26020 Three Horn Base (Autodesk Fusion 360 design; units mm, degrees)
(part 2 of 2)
sketch "Branding Profile 1" plane through (0, -3.9688, 0) normal (0, -1, 0) x axis (1, 0, 0)
  line L1 (-31.5508, 186.9488) -> (-36.5959, 184.036)
  line L2 (-12.7, 222.2105) -> (-12.7, 219.5994)
  line L3 (-155.7294, 176.3331) -> (-12.7, 222.2105)
  line L4 (-155.575, 165.6244) -> (-155.575, 174.625)
  line L5 (-56.8347, 186.3809) -> (-136.4794, 160.8345)
  line L6 (-56.8347, 186.3809) -> (-56.3499, 184.8693)
  line L7 (-136.4794, 160.8345) -> (-56.8347, 186.3809)
  line L8 (-135.9945, 159.3229) -> (-136.4794, 160.8345)
  line L9 (-56.3499, 184.8693) -> (-135.9945, 159.3229)
  curve K1 (-40.4845, 180.5516) -> (-40.1097, 176.7109)
  line L10 (-56.8347, 186.3809) -> (-56.3499, 184.8693)
  line L11 (-39.7709, 172.7761) -> (-39.77, 172.7761)
  curve K2 (-40.1097, 176.7109) -> (-39.77, 172.7761)
  curve K3 (-140.7089, 150.0191) -> (-141.9327, 154.2492)
  line L12 (-139.7584, 150.4844) -> (-140.7089, 150.0191)
  line L13 (-135.9945, 159.3229) -> (-136.4794, 160.8345)
  line L14 (-12.7, 222.2105) -> (-13.6697, 225.2338)
  line L15 (-156.6991, 179.3564) -> (-13.6697, 225.2338)
  line L16 (-156.6991, 179.3564) -> (-155.7294, 176.3331)
  line L17 (-12.7, 222.2105) -> (-155.7294, 176.3331)
  line L18 (136.4794, 160.8345) -> (56.8347, 186.3809)
  line L19 (155.575, 174.625) -> (155.575, 165.6244)
  line L20 (12.7, 222.2105) -> (155.7294, 176.3331)
  line L21 (12.7, 219.5994) -> (12.7, 222.2105)
  line L22 (36.5959, 184.036) -> (31.5508, 186.9488)
  curve K4 (40.4845, 180.5516) -> (40.1097, 176.7109)
  curve K5 (40.1097, 176.7109) -> (39.77, 172.7761)
  line L23 (39.7709, 172.7761) -> (39.77, 172.7761)
  line L24 (56.8347, 186.3809) -> (56.3499, 184.8693)
  line L25 (56.8347, 186.3809) -> (56.3499, 184.8693)
  line L26 (135.9945, 159.3229) -> (56.3499, 184.8693)
  line L27 (135.9945, 159.3229) -> (136.4794, 160.8345)
  line L28 (56.8347, 186.3809) -> (136.4794, 160.8345)
  line L29 (12.7, 222.2105) -> (13.6697, 225.2338)
  line L30 (155.7294, 176.3331) -> (12.7, 222.2105)
  line L31 (156.6991, 179.3564) -> (155.7294, 176.3331)
  line L32 (13.6697, 225.2338) -> (156.6991, 179.3564)
  curve K6 (140.7089, 150.0191) -> (141.9327, 154.2492)
  line L33 (135.9945, 159.3229) -> (136.4794, 160.8345)
  line L34 (139.7584, 150.4844) -> (140.7089, 150.0191)
  line L35 (155.575, 166.3797) -> (26.6705, 207.7264)
  line L36 (152.4473, 164.0486) -> (28.8842, 203.682)
  line L37 (54.1881, 192.6481) -> (54.5517, 193.7819)
  line L38 (89.7232, 181.2501) -> (54.1881, 192.6481)
  line L39 (90.0869, 182.3838) -> (89.7232, 181.2501)
  line L40 (54.5517, 193.7819) -> (90.0869, 182.3838)
  line L41 (56.0063, 198.3168) -> (54.5517, 193.7819)
  line L42 (91.5415, 186.9187) -> (90.0869, 182.3838)
  line L43 (0, 0) -> (0, 190.5)
  line L44 (-155.575, 166.3797) -> (-26.6705, 207.7264)
  line L45 (-152.4473, 164.0486) -> (-28.8842, 203.682)
  line L46 (-77.4266, 178.1088) -> (-84.2147, 199.2718)
  line L47 (-96.9368, 188.7387) -> (-96.6586, 188.1926)
  line L48 (-96.5087, 190.4673) -> (-99.5707, 189.4851)
  line L49 (-98.0524, 187.6309) -> (-98.1815, 188.0333)
  line L50 (-98.1815, 188.0333) -> (-98.2508, 188.2492)
  line L51 (-86.6058, 181.1557) -> (-90.1291, 180.4947)
  line L52 (-103.3725, 187.5824) -> (-101.9285, 187.6866)
  line L53 (-107.3077, 171.8767) -> (-112.6516, 188.5369)
  line L54 (-82.1059, 190.2631) -> (-81.3786, 187.9956)
  line L55 (-89.3894, 182.2487) -> (-86.9965, 182.6976)
  line L56 (-103.5297, 173.7717) -> (-105.8079, 171.5106)
  line L57 (-83.5117, 181.3674) -> (-84.351, 181.3852)
  line L58 (-97.996, 178.515) -> (-97.8569, 178.0814)
  line L59 (-102.0903, 183.4417) -> (-102.4361, 183.3308)
  line L60 (-87.2075, 194.612) -> (-83.1254, 181.8854)
  line L61 (-81.1219, 188.4947) -> (-80.5926, 188.6645)
  line L62 (-82.1059, 190.2631) -> (-83.84, 195.6696)
  line L63 (-96.9704, 182.637) -> (-97.3337, 182.5205)
  line L64 (-92.3853, 180.179) -> (-93.576, 183.8912)
  line L65 (-97.5904, 182.0213) -> (-96.569, 178.8371)
  line L66 (-95.8113, 180.3226) -> (-96.4713, 182.3803)
  line L67 (-96.0699, 178.5804) -> (-92.642, 179.6799)
  line L68 (-94.2583, 180.8208) -> (-94.9263, 182.9036)
  line L69 (-94.52, 180.3118) -> (-95.3023, 180.0609)
  line L70 (-93.2211, 191.7577) -> (-93.9769, 191.5153)
  line L71 (-97.989, 188.7582) -> (-97.421, 188.9404)
  line L72 (-99.114, 186.4379) -> (-99.8914, 188.8615)
  line L73 (-95.496, 188.6717) -> (-95.9857, 190.1983)
  line L74 (-105.4225, 174.2801) -> (-104.5257, 175.1702)
  line L75 (-100.2676, 177.79) -> (-98.7685, 178.7857)
  line L76 (-101.2759, 182.5708) -> (-101.4496, 183.1122)
  line L77 (-102.2104, 175.7615) -> (-106.2084, 188.2258)
  line L78 (-102.1328, 189.1978) -> (-105.727, 188.9383)
  line L79 (-111.2105, 188.9864) -> (-111.9726, 189.2226)
  line L80 (-103.4599, 174.9101) -> (-103.3418, 174.5419)
  line L81 (-103.0768, 183.6603) -> (-102.2807, 181.1784)
  line L82 (-106.3418, 174.5044) -> (-110.883, 188.6622)
  line L83 (-101.429, 188.426) -> (-101.5503, 188.8042)
  line L84 (-101.3112, 178.1557) -> (-102.2807, 181.1784)
  line L85 (-98.0769, 177.4536) -> (-101.1723, 175.3977)
  line L86 (-101.9512, 181.8191) -> (-101.6054, 181.93)
  line L87 (-103.0768, 183.6603) -> (-104.025, 186.6165)
  line L88 (-76.5065, 181.703) -> (-76.7732, 182.5347)
  line L89 (-89.8405, 182.5175) -> (-92.722, 191.501)
  line L90 (-80.3359, 189.1636) -> (-80.5783, 189.9194)
  line L91 (-88.4954, 194.306) -> (-87.8231, 194.8087)
  line L92 (-81.8448, 198.0238) -> (-82.108, 198.8442)
  line L93 (-80.6622, 181.6375) -> (-76.9319, 181.1878)
  line L94 (-91.0313, 181.0324) -> (-94.2336, 191.0162)
  line L95 (-83.7208, 196.0918) -> (-81.964, 197.6016)
  line L96 (-81.323, 182.1832) -> (-85.7039, 195.8413)
  line L97 (-81.0775, 190.1761) -> (-81.6067, 190.0064)
  line L98 (-95.5178, 183.7123) -> (-98.8586, 186.0887)
  line L99 (-94.1674, 184.6999) -> (-97.797, 187.2817)
  line L100 (-79.8972, 183.3773) -> (-81.3786, 187.9956)
  line L101 (-82.7445, 199.024) -> (-85.4654, 196.6857)
  line L102 (-84.7205, 181.6608) -> (-88.6357, 193.8669)
  line L103 (-86.5454, 182.4287) -> (-86.3011, 181.667)
  line L104 (-77.1036, 182.8075) -> (-79.5668, 183.1045)
  arc A1 centre (-30.2459, 173.0375) radius 12.7 clockwise from (-40.4845, 180.5516) to (-36.5959, 184.036)
  arc A2 centre (0, 190.5) radius 31.75 clockwise from (-31.5508, 186.9488) to (-12.7, 219.5994)
  arc A3 centre (-165.1, 174.625) radius 9.525 clockwise from (-155.7294, 176.3331) to (-155.575, 174.625)
  arc A4 centre (-168.275, 136.525) radius 31.75 clockwise from (-155.575, 165.6244) to (-141.9327, 154.2492)
  arc A5 centre (-134.0551, 153.2763) radius 7.9375 clockwise from (-141.9327, 154.2492) to (-136.4794, 160.8345)
  arc A6 centre (-52.4709, 172.7761) radius 14.2875 clockwise from (-56.8347, 186.3809) to (-40.4845, 180.5516)
  arc A7 centre (-52.4709, 172.7761) radius 14.2875 clockwise from (-56.8347, 186.3809) to (-40.4845, 180.5516)
  arc A8 centre (-52.4709, 172.7761) radius 12.7 clockwise from (-56.3499, 184.8693) to (-39.7709, 172.7761)
  arc A9 centre (-134.0551, 153.2763) radius 6.35 clockwise from (-139.7584, 150.4844) to (-135.9945, 159.3229)
  arc A10 centre (-134.0551, 153.2763) radius 7.9375 clockwise from (-141.9327, 154.2492) to (-136.4794, 160.8345)
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  point P79 (155.575, 166.3797)
  point P86 (56.0063, 198.3168)
  point P87 (91.5415, 186.9187)
  point P56 (0, 190.5)
  point P88 (0, 190.5)
  point P1 (0, 0)
  point P89 (0, 0)
  point P78 (26.6705, 207.7264)
  point P90 (-26.6705, 207.7264)
  point P91 (-155.575, 166.3797)
  point P80 (28.8842, 203.682)
  point P92 (-28.8842, 203.682)
  point P81 (152.4473, 164.0486)
  point P93 (-152.4473, 164.0486)
  point P94 (-84.2147, 199.2718)
  point P95 (-77.4266, 178.1088)
  point P124 (-106.3418, 174.5044)
  point P138 (-106.3418, 174.5044)
  point P220 (-89.8405, 182.5175)
  point P223 (-89.8405, 182.5175)
  point P239 (-80.4571, 189.5415)
  point P198 (-81.323, 182.1832)
  point P240 (-81.323, 182.1832)
  point P82 (54.5517, 193.7819)
  point P83 (54.1881, 192.6481)
  parallel L32 L35
  coincident L19 P79
  parallel L35 L36
  perpendicular L37 L38
  perpendicular L38 L39
  perpendicular L37 L40
  parallel L36 L40
  coincident L35 P86
  perpendicular L35 L41
  coincident L35 P87
  perpendicular L35 L42
  coincident P56 P88
  coincident P1 P89
  symmetric P78 L43 P90
  symmetric P79 L43 P91
  symmetric P80 L43 P92
  symmetric P81 L43 P93
  midpoint L3 P94
  coincident L9 P95
  perpendicular L9 L46
  parallel L56 L74
  coincident P124 P138
  parallel L52 L78
  parallel L75 L85
  parallel L49 L50
  parallel L98 L99
  parallel L51 L55
  coincident P220 P223
  parallel L95 L101
  midpoint P239 L90
  parallel L93 L104
  coincident P198 P240
  dimension "d207" distance L26 L35 = 12.7 (= "( 1 / 2 ) * 1 in")
  dimension "d208" distance L35 L36 = 3.175 (= "( 1 / 8 ) * 1 in")
  dimension "d210" distance P82 P83 = 1.1906 (= "( 3 / 64 ) * 1 in")
  dimension "d211" distance L36 L40 = 1.5875 (= "( 1 / 16 ) * 1 in")
  dimension "d277" angle L53 L79 = 55
  dimension "d278" distance L53 L82 = 1.7223
  dimension "d279" angle L53 L56 = 63
  dimension "d280" distance L77 L87 = 1.5875 (= "( 1 / 16 ) * 1 in")
  dimension "d281" radius = 0.5095
  dimension "d282" radius = 0.5095 (= "d281")
  dimension "d283" radius = 0.5095 (= "d281")
  dimension "d284" radius = 0.5095 (= "d281")
  dimension "d285" distance L59 L86 = 1.5875 (= "( 1 / 16 ) * 1 in")
  dimension "d287" radius = 0.4159
  dimension "d288" angle L47 L73 = 9.219
  dimension "d289" radius = 0.6307
  dimension "d290" radius = 0.4047
  dimension "d291" radius = 0.4047 (= "d290")
  dimension "d292" radius = 0.6854
  dimension "d293" radius = 0.6854 (= "d292")
  dimension "d294" distance L98 L99 = 1.5875 (= "( 1 / 16 ) * 1 in")
  dimension "d295" distance L64 L68 = 1.5875 (= "( 1 / 16 ) * 1 in")
  dimension "d296" radius = 1.5875 (= "( 1 / 16 ) * 1 in")
  dimension "d297" radius = 1.5875 (= "d296")
  dimension "d298" radius = 0.3969 (= "( 1 / 64 ) * 1 in")
  dimension "d299" radius = 0.3969 (= "( 1 / 64 ) * 1 in")
  dimension "d300" radius = 0.3969 (= "( 1 / 64 ) * 1 in")
  dimension "d301" radius = 0.3969 (= "d300")
  dimension "d302" radius = 0.4047 (= "d290")
  dimension "d303" radius = 0.4047 (= "d302")
  dimension "d304" distance L65 L66 = 1.1753 (= "d305")
  dimension "d305" distance L48 L71 = 1.1753
  dimension "d306" distance L67 L69 = 1.1753 (= "d305")
  dimension "d307" radius = 0.3969 (= "( 1 / 64 ) * 1 in")
  dimension "d308" radius = 0.3969 (= "d307")
  dimension "d309" distance L89 L94 = 1.5875 (= "( 1 / 16 ) * 1 in")
  dimension "d310" radius = 0.7937 (= "( 1 / 32 ) * 1 in")
  dimension "d311" radius = 0.3969 (= "( 1 / 64 ) * 1 in")
  dimension "d312" radius = 0.3969 (= "( 1 / 64 ) * 1 in")
  dimension "d313" distance L51 L55 = 1.5875 (= "( 1 / 16 ) * 1 in")
  dimension "d314" radius = 0.3969 (= "( 1 / 64 ) * 1 in")
  dimension "d317" radius = 0.3969 (= "( 1 / 64 ) * 1 in")
  dimension "d318" angle L57 L102 = 109
  dimension "d319" radius = 0.3969 (= "( 1 / 64 ) * 1 in")
  dimension "d320" distance L60 L102 = 1.5875 (= "( 1 / 16 ) * 1 in")
  dimension "d321" radius = 0.3969 (= "( 1 / 64 ) * 1 in")
  dimension "d322" radius = 0.3969 (= "( 1 / 64 ) * 1 in")
  dimension "d323" angle L91 L102 = 109
  dimension "d324" radius = 0.7937 (= "( 1 / 32 ) * 1 in")
  dimension "d326" radius = 0.3969 (= "( 1 / 64 ) * 1 in")
  dimension "d327" radius = 0.3969 (= "( 1 / 64 ) * 1 in")
  dimension "d328" distance L95 L101 = 1.5875 (= "( 1 / 16 ) * 1 in")
  dimension "d329" distance L62 L96 = 1.7223 (= "d278")
  dimension "d330" radius = 0.3969 (= "( 1 / 64 ) * 1 in")
  dimension "d331" radius = 0.3969 (= "d330")
  dimension "d332" distance L62 L90 = 1.3496
  dimension "d333" radius = 0.3969 (= "d330")
  dimension "d334" distance L61 L97 = 1.5875 (= "( 1 / 16 ) * 1 in")
  dimension "d335" radius = 0.3969 (= "d330")
  dimension "d336" radius = 0.3969 (= "( 1 / 64 ) * 1 in")
  dimension "d337" radius = 0.3969 (= "d336")
  dimension "d338" radius = 0.3969 (= "d337")
  dimension "d339" angle L88 L104 = 114.659
  dimension "d340" radius = 0.3969 (= "( 1 / 64 ) * 1 in")
  dimension "d342" distance L93 L104 = 1.5875 (= "( 1 / 16 ) * 1 in")
  dimension "d209" Text1-Height = 11.1125 (= "( 7 / 16 ) * 1 in")
extrude "Extrude17" add sketch "Branding Profile 1" along normal blind 0.3969 (= "( 1 / 64 ) * 1 in") taper -30
extrude "Extrude18" add sketch "Branding Profile 1" profile of L37 L38 L39 L40 along normal blind 0.3969 (= "( 1 / 64 ) * 1 in") taper -25
sketch "Branding Profile 2" plane through (0, 3.9688, 0) normal (0, 1, 0) x axis (-1, 0, 0)
  line L1 (-31.5508, 186.9488) -> (-36.5959, 184.036)
  line L2 (-12.7, 222.2105) -> (-12.7, 219.5994)
  line L3 (-155.7294, 176.3331) -> (-12.7, 222.2105)
  line L4 (-155.575, 165.6244) -> (-155.575, 174.625)
  line L5 (-56.8347, 186.3809) -> (-136.4794, 160.8345)
  line L6 (136.4794, 160.8345) -> (56.8347, 186.3809)
  line L7 (155.575, 174.625) -> (155.575, 165.6244)
  line L8 (12.7, 222.2105) -> (155.7294, 176.3331)
  line L9 (12.7, 219.5994) -> (12.7, 222.2105)
  line L10 (36.5959, 184.036) -> (31.5508, 186.9488)
  curve K1 (40.4845, 180.5516) -> (40.1097, 176.7109)
  curve K2 (40.1097, 176.7109) -> (39.77, 172.7761)
  line L11 (39.7709, 172.7761) -> (39.77, 172.7761)
  line L12 (56.8347, 186.3809) -> (56.3499, 184.8693)
  line L13 (56.8347, 186.3809) -> (136.4794, 160.8345)
  line L14 (56.8347, 186.3809) -> (56.3499, 184.8693)
  line L15 (135.9945, 159.3229) -> (56.3499, 184.8693)
  line L16 (135.9945, 159.3229) -> (136.4794, 160.8345)
  line L17 (56.8347, 186.3809) -> (136.4794, 160.8345)
  line L18 (12.7, 222.2105) -> (13.6697, 225.2338)
  line L19 (155.7294, 176.3331) -> (12.7, 222.2105)
  line L20 (156.6991, 179.3564) -> (155.7294, 176.3331)
  line L21 (13.6697, 225.2338) -> (156.6991, 179.3564)
  line L22 (-12.7, 222.2105) -> (-13.6697, 225.2338)
  line L23 (-156.6991, 179.3564) -> (-13.6697, 225.2338)
  line L24 (-156.6991, 179.3564) -> (-155.7294, 176.3331)
  line L25 (-12.7, 222.2105) -> (-155.7294, 176.3331)
  curve K3 (-40.4845, 180.5516) -> (-40.1097, 176.7109)
  line L26 (-56.8347, 186.3809) -> (-56.3499, 184.8693)
  line L27 (-39.7709, 172.7761) -> (-39.77, 172.7761)
  curve K4 (-40.1097, 176.7109) -> (-39.77, 172.7761)
  line L28 (-56.8347, 186.3809) -> (-56.3499, 184.8693)
  line L29 (-136.4794, 160.8345) -> (-56.8347, 186.3809)
  line L30 (-135.9945, 159.3229) -> (-136.4794, 160.8345)
  line L31 (-56.3499, 184.8693) -> (-135.9945, 159.3229)
  curve K5 (-140.7089, 150.0191) -> (-141.9327, 154.2492)
  line L32 (-139.7584, 150.4844) -> (-140.7089, 150.0191)
  line L33 (-135.9945, 159.3229) -> (-136.4794, 160.8345)
  curve K6 (140.7089, 150.0191) -> (141.9327, 154.2492)
  line L34 (135.9945, 159.3229) -> (136.4794, 160.8345)
  line L35 (139.7584, 150.4844) -> (140.7089, 150.0191)
  line L36 (-155.575, 166.3797) -> (-26.6705, 207.7264)
  line L37 (-152.4473, 164.0486) -> (-28.8842, 203.682)
  line L38 (155.575, 166.3797) -> (26.6705, 207.7264)
  line L39 (152.4473, 164.0486) -> (28.8842, 203.682)
  line L40 (77.4266, 178.1088) -> (84.2147, 199.2718)
  line L41 (54.1645, 192.6557) -> (54.5281, 193.7894)
  line L42 (89.7636, 181.2371) -> (54.1645, 192.6557)
  line L43 (90.1272, 182.3708) -> (89.7636, 181.2371)
  line L44 (54.5281, 193.7894) -> (90.1272, 182.3708)
  line L45 (55.9827, 198.3244) -> (54.5281, 193.7894)
  line L46 (91.5818, 186.9058) -> (90.1272, 182.3708)
  line L47 (0, 0) -> (0, 190.5)
  line L48 (-77.4266, 178.1088) -> (-84.2147, 199.2718)
  line L49 (-82.032, 189.9669) -> (-81.3047, 187.6994)
  line L50 (-80.5883, 181.3414) -> (-76.858, 180.8916)
  line L51 (-92.3114, 179.8829) -> (-93.5021, 183.595)
  line L52 (-97.5165, 181.7252) -> (-96.4951, 178.5409)
  line L53 (-94.1844, 180.5246) -> (-94.8524, 182.6074)
  line L54 (-96.8965, 182.3409) -> (-97.2598, 182.2243)
  line L55 (-95.7374, 180.0265) -> (-96.3974, 182.0842)
  line L56 (-94.4461, 180.0157) -> (-95.2284, 179.7647)
  line L57 (-95.996, 178.2842) -> (-92.5681, 179.3838)
  line L58 (-97.9151, 188.462) -> (-97.3471, 188.6442)
  line L59 (-96.4348, 190.1711) -> (-99.4968, 189.189)
  line L60 (-81.0036, 189.88) -> (-81.5328, 189.7102)
  line L61 (-82.032, 189.9669) -> (-83.7661, 195.3735)
  line L62 (-87.1336, 194.3159) -> (-83.0515, 181.5893)
  line L63 (-83.6469, 195.7957) -> (-81.8901, 197.3054)
  line L64 (-77.0297, 182.5113) -> (-79.4929, 182.8083)
  line L65 (-81.048, 188.1986) -> (-80.5187, 188.3683)
  line L66 (-80.262, 188.8675) -> (-80.5044, 189.6233)
  line L67 (-76.4326, 181.4068) -> (-76.6993, 182.2385)
  line L68 (-94.0935, 184.4038) -> (-97.7231, 186.9855)
  line L69 (-103.0029, 183.3642) -> (-103.9511, 186.3204)
  line L70 (-98.1076, 187.7372) -> (-98.1769, 187.9531)
  line L71 (-95.4439, 183.4162) -> (-98.7847, 185.7925)
  line L72 (-96.8629, 188.4426) -> (-96.5847, 187.8965)
  line L73 (-101.3551, 188.1299) -> (-101.4764, 188.508)
  line L74 (-102.1365, 175.4653) -> (-106.1345, 187.9297)
  line L75 (-99.0401, 186.1417) -> (-99.8175, 188.5653)
  line L76 (-89.3155, 181.9525) -> (-86.9226, 182.4014)
  line L77 (-90.9574, 180.7362) -> (-94.1597, 190.72)
  line L78 (-95.4221, 188.3755) -> (-95.9118, 189.9022)
  line L79 (-89.7666, 182.2214) -> (-92.6481, 191.2049)
  line L80 (-98.003, 177.1575) -> (-101.0984, 175.1015)
  line L81 (-101.202, 182.2747) -> (-101.3757, 182.816)
  line L82 (-111.1366, 188.6903) -> (-111.8987, 188.9264)
  line L83 (-93.1472, 191.4616) -> (-93.903, 191.2191)
  line L84 (-86.5319, 180.8595) -> (-90.0552, 180.1985)
  line L85 (-97.9785, 187.3347) -> (-98.1076, 187.7372)
  line L86 (-101.2373, 177.8596) -> (-102.2068, 180.8822)
  line L87 (-103.2986, 187.2862) -> (-101.8546, 187.3904)
  line L88 (-102.0589, 188.9016) -> (-105.6531, 188.6422)
  line L89 (-102.0164, 183.1455) -> (-102.3622, 183.0346)
  line L90 (-103.4558, 173.4756) -> (-105.734, 171.2145)
  line L91 (-103.386, 174.6139) -> (-103.2679, 174.2457)
  line L92 (-106.2679, 174.2083) -> (-110.8091, 188.366)
  line L93 (-100.1937, 177.4939) -> (-98.6946, 178.4895)
  line L94 (-103.0029, 183.3642) -> (-102.2068, 180.8822)
  line L95 (-105.3486, 173.9839) -> (-104.4518, 174.8741)
  line L96 (-107.2338, 171.5805) -> (-112.5777, 188.2407)
  line L97 (-101.8773, 181.523) -> (-101.5315, 181.6339)
  line L98 (-97.9221, 178.2188) -> (-97.783, 177.7853)
  line L99 (-82.6706, 198.7279) -> (-85.3915, 196.3896)
  line L100 (-79.8233, 183.0811) -> (-81.3047, 187.6994)
  line L101 (-81.2491, 181.887) -> (-85.63, 195.5451)
  line L102 (-81.7709, 197.7276) -> (-82.0341, 198.5481)
  line L103 (-86.4715, 182.1326) -> (-86.2272, 181.3708)
  line L104 (-83.4378, 181.0713) -> (-84.2771, 181.0891)
  line L105 (-88.4215, 194.0098) -> (-87.7492, 194.5125)
  line L106 (-84.6466, 181.3647) -> (-88.5618, 193.5708)
  arc A1 centre (-30.2459, 173.0375) radius 12.7 clockwise from (-40.4845, 180.5516) to (-36.5959, 184.036)
  arc A2 centre (0, 190.5) radius 31.75 clockwise from (-31.5508, 186.9488) to (-12.7, 219.5994)
  arc A3 centre (-165.1, 174.625) radius 9.525 clockwise from (-155.7294, 176.3331) to (-155.575, 174.625)
  arc A4 centre (-168.275, 136.525) radius 31.75 clockwise from (-155.575, 165.6244) to (-141.9327, 154.2492)
  arc A5 centre (-134.0551, 153.2763) radius 7.9375 clockwise from (-141.9327, 154.2492) to (-136.4794, 160.8345)
  arc A6 centre (-52.4709, 172.7761) radius 14.2875 clockwise from (-56.8347, 186.3809) to (-40.4845, 180.5516)
  arc A7 centre (30.2459, 173.0375) radius 12.7 clockwise from (36.5959, 184.036) to (40.4845, 180.5516)
  arc A8 centre (52.4709, 172.7761) radius 14.2875 clockwise from (40.4845, 180.5516) to (56.8347, 186.3809)
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  point P94 (55.9827, 198.3244)
  point P95 (91.5818, 186.9058)
  point P35 (0, 190.5)
  point P96 (0, 190.5)
  point P1 (0, 0)
  point P97 (0, 0)
  point P88 (84.2147, 199.2718)
  point P98 (-84.2147, 199.2718)
  point P89 (77.4266, 178.1088)
  point P99 (-77.4266, 178.1088)
  point P128 (-106.2679, 174.2083)
  point P142 (-106.2679, 174.2083)
  point P224 (-89.7666, 182.2214)
  point P227 (-89.7666, 182.2214)
  point P243 (-80.3832, 189.2454)
  point P202 (-81.2491, 181.887)
  point P244 (-81.2491, 181.887)
  point P90 (54.5281, 193.7894)
  point P91 (54.1645, 192.6557)
  perpendicular L41 L42
  perpendicular L42 L43
  perpendicular L41 L44
  parallel L39 L44
  coincident L38 P94
  perpendicular L38 L45
  coincident L38 P95
  perpendicular L38 L46
  coincident P35 P96
  coincident P1 P97
  symmetric P88 L47 P98
  symmetric P89 L47 P99
  parallel L90 L95
  coincident P128 P142
  parallel L87 L88
  parallel L80 L93
  parallel L70 L85
  parallel L68 L71
  parallel L76 L84
  coincident P224 P227
  parallel L63 L99
  midpoint P243 L66
  parallel L50 L64
  coincident P202 P244
  dimension "d315" distance P90 P91 = 1.1906 (= "( 3 / 64 ) * 1 in")
  dimension "d316" distance L39 L44 = 1.5875 (= "( 1 / 16 ) * 1 in")
  dimension "d325" angle L82 L96 = 55
  dimension "d341" distance L92 L96 = 1.7223
  dimension "d343" angle L90 L96 = 63
  dimension "d344" distance L69 L74 = 1.5875 (= "( 1 / 16 ) * 1 in")
  dimension "d345" radius = 0.5095
  dimension "d346" radius = 0.5095 (= "d281")
  dimension "d347" radius = 0.5095 (= "d281")
  dimension "d348" radius = 0.5095 (= "d281")
  dimension "d349" distance L89 L97 = 1.5875 (= "( 1 / 16 ) * 1 in")
  dimension "d350" radius = 0.4159
  dimension "d351" angle L72 L78 = 9.219
  dimension "d352" radius = 0.6307
  dimension "d353" radius = 0.4047
  dimension "d354" radius = 0.4047 (= "d290")
  dimension "d355" radius = 0.6854
  dimension "d356" radius = 0.6854 (= "d292")
  dimension "d357" distance L68 L71 = 1.5875 (= "( 1 / 16 ) * 1 in")
  dimension "d358" distance L51 L53 = 1.5875 (= "( 1 / 16 ) * 1 in")
  dimension "d359" radius = 1.5875 (= "( 1 / 16 ) * 1 in")
  dimension "d360" radius = 1.5875 (= "d296")
  dimension "d361" radius = 0.3969 (= "( 1 / 64 ) * 1 in")
  dimension "d362" radius = 0.3969 (= "( 1 / 64 ) * 1 in")
  dimension "d363" radius = 0.3969 (= "( 1 / 64 ) * 1 in")
  dimension "d364" radius = 0.3969 (= "d300")
  dimension "d365" radius = 0.4047 (= "d290")
  dimension "d366" radius = 0.4047 (= "d302")
  dimension "d367" distance L52 L55 = 1.1753 (= "d305")
  dimension "d368" distance L58 L59 = 1.1753
  dimension "d369" distance L56 L57 = 1.1753 (= "d305")
  dimension "d370" radius = 0.3969 (= "( 1 / 64 ) * 1 in")
  dimension "d371" radius = 0.3969 (= "d307")
  dimension "d372" distance L77 L79 = 1.5875 (= "( 1 / 16 ) * 1 in")
  dimension "d373" radius = 0.7937 (= "( 1 / 32 ) * 1 in")
  dimension "d374" radius = 0.3969 (= "( 1 / 64 ) * 1 in")
  dimension "d375" radius = 0.3969 (= "( 1 / 64 ) * 1 in")
  dimension "d376" distance L76 L84 = 1.5875 (= "( 1 / 16 ) * 1 in")
  dimension "d377" radius = 0.3969 (= "( 1 / 64 ) * 1 in")
  dimension "d378" radius = 0.3969 (= "( 1 / 64 ) * 1 in")
  dimension "d379" angle L104 L106 = 109
  dimension "d380" radius = 0.3969 (= "( 1 / 64 ) * 1 in")
  dimension "d381" distance L62 L106 = 1.5875 (= "( 1 / 16 ) * 1 in")
  dimension "d382" radius = 0.3969 (= "( 1 / 64 ) * 1 in")
  dimension "d383" radius = 0.3969 (= "( 1 / 64 ) * 1 in")
  dimension "d384" angle L105 L106 = 109
  dimension "d385" radius = 0.7937 (= "( 1 / 32 ) * 1 in")
  dimension "d386" radius = 0.3969 (= "( 1 / 64 ) * 1 in")
  dimension "d387" radius = 0.3969 (= "( 1 / 64 ) * 1 in")
  dimension "d388" distance L63 L99 = 1.5875 (= "( 1 / 16 ) * 1 in")
  dimension "d389" distance L61 L101 = 1.7223 (= "d278")
  dimension "d390" radius = 0.3969 (= "( 1 / 64 ) * 1 in")
  dimension "d391" radius = 0.3969 (= "d330")
  dimension "d392" distance L61 L66 = 1.3496
  dimension "d393" radius = 0.3969 (= "d330")
  dimension "d394" distance L60 L65 = 1.5875 (= "( 1 / 16 ) * 1 in")
  dimension "d395" radius = 0.3969 (= "d330")
  dimension "d396" radius = 0.3969 (= "( 1 / 64 ) * 1 in")
  dimension "d397" radius = 0.3969 (= "d336")
  dimension "d398" radius = 0.3969 (= "d337")
  dimension "d399" angle L64 L67 = 114.659
  dimension "d400" radius = 0.3969 (= "( 1 / 64 ) * 1 in")
  dimension "d401" distance L50 L64 = 1.5875 (= "( 1 / 16 ) * 1 in")
  dimension "d286" Text1-Height = 11.1125 (= "( 7 / 16 ) * 1 in")
extrude "Extrude19" add sketch "Branding Profile 2" along normal blind 0.3969 (= "( 1 / 64 ) * 1 in") taper -30
extrude "Extrude20" add sketch "Branding Profile 2" profile of L41 L42 L43 L44 along normal blind 0.3969 (= "( 1 / 64 ) * 1 in") taper -25
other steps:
create_component "CreateComponent1"
named bodies: "26020 Three Horn Base", "Plug Weld"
